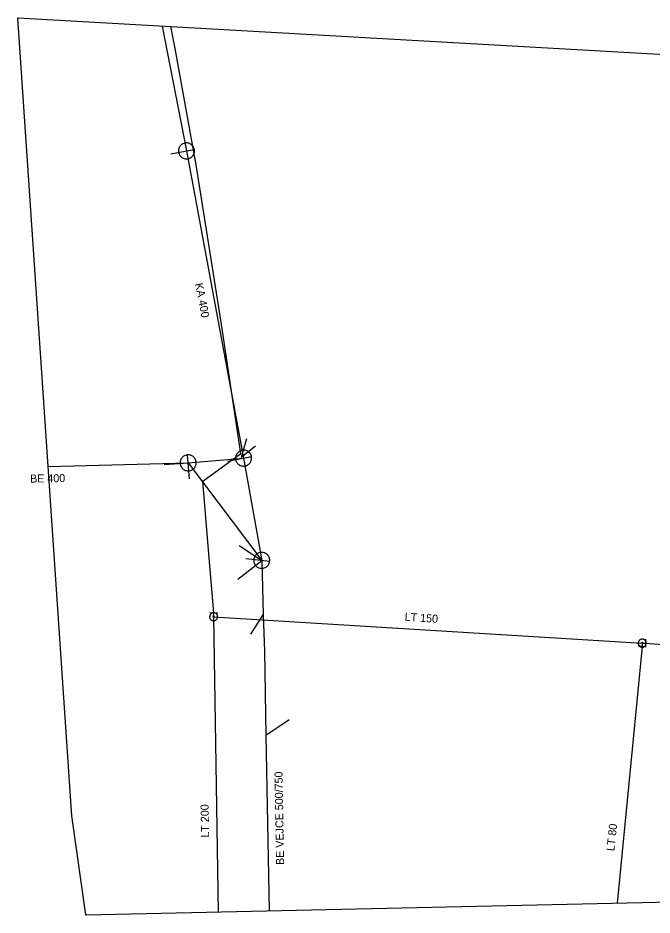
# Model space of a CAD drawing. Extents: x -716525 to -716349, y -954127 to -954015.
# Drawn here: x -716525 to -716445.8, y -954126.6 to -954014.6 of the extents above; entities that cross this region are included whole.
import ezdxf

# ---------------------------------------------------------------- set-up
doc = ezdxf.new("R2010")
doc.units = 0
for name, color, linetype in [('Vrstva 1', 7, 'Continuous'), ('Vrstva 11', 7, 'Continuous'), ('Vrstva 14', 7, 'Continuous'), ('Vrstva 17', 7, 'Continuous'), ('Vrstva 22', 7, 'Continuous'), ('Vrstva 34', 7, 'Continuous'), ('Vrstva 47', 7, 'Continuous'), ('Vrstva 63', 7, 'Continuous')]:
    doc.layers.add(name, color=color, linetype=linetype)

msp = doc.modelspace()

# ---------------------------------------------------------------- linework, layer by layer
at = {"layer": 'Vrstva 11'}
for points in [[(-716496.487, -954067.156), (-716497.136, -954069.488)], [(-716495.347, -954068.067), (-716497.136, -954069.488)], [(-716506.77, -954070.359), (-716503.76, -954070.149)], [(-716497.398, -954080.489), (-716494.565, -954082.325)], [(-716497.532, -954084.686), (-716494.565, -954082.325)], [(-716495.917, -954091.543), (-716494.395, -954089.144)], [(-716491.13, -954102.256), (-716494.039, -954104.18)]]:
    msp.add_lwpolyline(points, dxfattribs=at)
at = {"layer": 'Vrstva 14'}
for points in [[(-716506.995, -954015.599), (-716503.969, -954031.19)], [(-716503.969, -954031.19), (-716496.829, -954069.559)], [(-716503.76, -954070.149), (-716496.829, -954069.559)], [(-716496.829, -954069.559), (-716494.565, -954082.325)], [(-716521.234, -954070.59), (-716503.76, -954070.149)], [(-716503.76, -954070.149), (-716494.565, -954082.325)], [(-716494.565, -954082.325), (-716494.395, -954089.144), (-716494.227, -954093.666), (-716494.039, -954104.18), (-716493.649, -954126.119)], [(-716500.572, -954089.369), (-716500.552, -954088.87)], [(-716447.02, -954092.67), (-716447.05, -954093.092)], [(-716447.02, -954092.67), (-716446.614, -954092.66)]]:
    msp.add_lwpolyline(points, dxfattribs=at)
at = {"layer": 'Vrstva 17'}
for points in [[(-716500.552, -954088.87), (-716501.256, -954080.524), (-716501.92, -954072.44), (-716497.19, -954068.969), (-716499.646, -954052.587), (-716502.776, -954032.943), (-716505.399, -954018.397), (-716505.935, -954015.659)], [(-716500.572, -954089.369), (-716500.007, -954126.26)], [(-716500.572, -954089.369), (-716447.02, -954092.67)], [(-716447.05, -954093.092), (-716450.147, -954125.154)], [(-716446.614, -954092.66), (-716441.116, -954093.066), (-716435.876, -954093.455), (-716424.218, -954094.18), (-716409.455, -954095.1), (-716395.355, -954095.978), (-716387.266, -954096.485), (-716378.456, -954097.125), (-716369.476, -954097.505), (-716352.497, -954098.776)]]:
    msp.add_lwpolyline(points, dxfattribs=at)
at = {"layer": 'Vrstva 22'}
for points in [[(-716503.778, -954032.171), (-716503.673, -954032.145), (-716503.57, -954032.106), (-716503.472, -954032.057), (-716503.38, -954031.998), (-716503.295, -954031.929), (-716503.218, -954031.851), (-716503.151, -954031.764), (-716503.093, -954031.672), (-716503.045, -954031.573), (-716503.009, -954031.47), (-716502.984, -954031.363), (-716502.972, -954031.254), (-716502.97, -954031.144), (-716502.981, -954031.036), (-716503.004, -954030.928), (-716503.038, -954030.825), (-716503.083, -954030.724), (-716503.139, -954030.63), (-716503.206, -954030.543), (-716503.281, -954030.464), (-716503.365, -954030.393), (-716503.455, -954030.332), (-716503.553, -954030.281), (-716503.654, -954030.24), (-716503.759, -954030.212), (-716503.868, -954030.195), (-716503.978, -954030.19), (-716504.086, -954030.197), (-716504.195, -954030.216), (-716504.3, -954030.246), (-716504.401, -954030.287), (-716504.496, -954030.341), (-716504.586, -954030.403), (-716504.669, -954030.475), (-716504.743, -954030.556), (-716504.807, -954030.644), (-716504.862, -954030.74), (-716504.906, -954030.84), (-716504.939, -954030.944), (-716504.959, -954031.052), (-716504.969, -954031.161), (-716504.966, -954031.27), (-716504.951, -954031.379), (-716504.924, -954031.485), (-716504.886, -954031.588), (-716504.837, -954031.685), (-716504.778, -954031.777), (-716504.708, -954031.863), (-716504.63, -954031.939), (-716504.545, -954032.007), (-716504.452, -954032.066), (-716504.353, -954032.113), (-716504.25, -954032.15), (-716504.144, -954032.174), (-716504.035, -954032.187), (-716503.925, -954032.188), (-716503.816, -954032.178), (-716503.778, -954032.171)], [(-716505.932, -954031.571), (-716502.987, -954030.999)], [(-716502.763, -954070.064), (-716502.778, -954069.956), (-716502.805, -954069.85), (-716502.844, -954069.747), (-716502.893, -954069.65), (-716502.953, -954069.557), (-716503.022, -954069.473), (-716503.101, -954069.396), (-716503.187, -954069.329), (-716503.28, -954069.271), (-716503.379, -954069.224), (-716503.482, -954069.188), (-716503.589, -954069.164), (-716503.698, -954069.151), (-716503.807, -954069.15), (-716503.917, -954069.162), (-716504.023, -954069.185), (-716504.128, -954069.219), (-716504.227, -954069.264), (-716504.321, -954069.322), (-716504.407, -954069.387), (-716504.487, -954069.463), (-716504.557, -954069.547), (-716504.619, -954069.638), (-716504.67, -954069.735), (-716504.709, -954069.836), (-716504.738, -954069.942), (-716504.754, -954070.051), (-716504.759, -954070.16), (-716504.752, -954070.27), (-716504.733, -954070.377), (-716504.703, -954070.482), (-716504.66, -954070.583), (-716504.608, -954070.679), (-716504.545, -954070.769), (-716504.471, -954070.851), (-716504.391, -954070.924), (-716504.302, -954070.989), (-716504.207, -954071.043), (-716504.107, -954071.087), (-716504.002, -954071.119), (-716503.895, -954071.14), (-716503.786, -954071.149), (-716503.676, -954071.145), (-716503.568, -954071.13), (-716503.461, -954071.103), (-716503.359, -954071.065), (-716503.261, -954071.016), (-716503.169, -954070.956), (-716503.084, -954070.886), (-716503.008, -954070.809), (-716502.94, -954070.723), (-716502.883, -954070.629), (-716502.835, -954070.531), (-716502.799, -954070.428), (-716502.774, -954070.321), (-716502.762, -954070.212), (-716502.761, -954070.102), (-716502.763, -954070.064)], [(-716503.59, -954072.142), (-716503.844, -954069.153)], [(-716498.795, -954069.924), (-716495.846, -954069.376)], [(-716496.646, -954070.542), (-716496.54, -954070.516), (-716496.437, -954070.478), (-716496.338, -954070.43), (-716496.246, -954070.372), (-716496.161, -954070.303), (-716496.083, -954070.225), (-716496.015, -954070.139), (-716495.957, -954070.047), (-716495.908, -954069.949), (-716495.871, -954069.846), (-716495.845, -954069.74), (-716495.832, -954069.63), (-716495.83, -954069.521), (-716495.84, -954069.412), (-716495.862, -954069.304), (-716495.896, -954069.201), (-716495.94, -954069.1), (-716495.995, -954069.006), (-716496.061, -954068.918), (-716496.135, -954068.838), (-716496.219, -954068.767), (-716496.308, -954068.705), (-716496.406, -954068.653), (-716496.507, -954068.612), (-716496.612, -954068.582), (-716496.72, -954068.565), (-716496.83, -954068.559), (-716496.939, -954068.565), (-716497.047, -954068.583), (-716497.152, -954068.613), (-716497.254, -954068.653), (-716497.35, -954068.705), (-716497.44, -954068.767), (-716497.523, -954068.838), (-716497.598, -954068.919), (-716497.663, -954069.007), (-716497.719, -954069.102), (-716497.763, -954069.201), (-716497.797, -954069.305), (-716497.818, -954069.413), (-716497.829, -954069.522), (-716497.827, -954069.631), (-716497.812, -954069.741), (-716497.786, -954069.847), (-716497.749, -954069.949), (-716497.701, -954070.047), (-716497.642, -954070.14), (-716497.573, -954070.226), (-716497.496, -954070.303), (-716497.411, -954070.372), (-716497.319, -954070.431), (-716497.22, -954070.479), (-716497.118, -954070.517), (-716497.011, -954070.542), (-716496.903, -954070.556), (-716496.793, -954070.558), (-716496.684, -954070.548), (-716496.646, -954070.542)], [(-716494.673, -954083.319), (-716494.564, -954083.324), (-716494.455, -954083.318), (-716494.346, -954083.3), (-716494.242, -954083.271), (-716494.14, -954083.23), (-716494.043, -954083.178), (-716493.953, -954083.115), (-716493.871, -954083.044), (-716493.796, -954082.964), (-716493.731, -954082.876), (-716493.675, -954082.782), (-716493.631, -954082.681), (-716493.598, -954082.577), (-716493.576, -954082.47), (-716493.566, -954082.36), (-716493.568, -954082.251), (-716493.581, -954082.142), (-716493.607, -954082.036), (-716493.645, -954081.933), (-716493.693, -954081.835), (-716493.752, -954081.742), (-716493.82, -954081.657), (-716493.898, -954081.579), (-716493.983, -954081.511), (-716494.076, -954081.452), (-716494.174, -954081.404), (-716494.278, -954081.367), (-716494.383, -954081.341), (-716494.493, -954081.327), (-716494.602, -954081.326), (-716494.711, -954081.335), (-716494.818, -954081.357), (-716494.922, -954081.39), (-716495.022, -954081.435), (-716495.117, -954081.491), (-716495.204, -954081.556), (-716495.285, -954081.63), (-716495.356, -954081.713), (-716495.418, -954081.803), (-716495.47, -954081.9), (-716495.512, -954082.001), (-716495.541, -954082.106), (-716495.559, -954082.215), (-716495.565, -954082.324), (-716495.559, -954082.433), (-716495.541, -954082.541), (-716495.512, -954082.647), (-716495.47, -954082.749), (-716495.418, -954082.845), (-716495.357, -954082.935), (-716495.285, -954083.018), (-716495.205, -954083.093), (-716495.118, -954083.158), (-716495.023, -954083.213), (-716494.923, -954083.258), (-716494.818, -954083.292), (-716494.711, -954083.313), (-716494.673, -954083.319)], [(-716496.553, -954082.108), (-716493.571, -954082.433)]]:
    msp.add_lwpolyline(points, dxfattribs=at)
at = {"layer": 'Vrstva 34'}
for points in [[(-716501.051, -954088.85), (-716500.052, -954088.89)], [(-716446.552, -954093.139), (-716447.547, -954093.043)], [(-716446.614, -954092.16), (-716446.614, -954093.16)]]:
    msp.add_lwpolyline(points, dxfattribs=at)
at = {"layer": 'Vrstva 47'}
for points in [[(-716500.583, -954089.868), (-716500.531, -954089.867), (-716500.479, -954089.86), (-716500.428, -954089.847), (-716500.379, -954089.83), (-716500.331, -954089.807), (-716500.287, -954089.779), (-716500.246, -954089.747), (-716500.208, -954089.711), (-716500.174, -954089.672), (-716500.144, -954089.628), (-716500.119, -954089.582), (-716500.1, -954089.533), (-716500.085, -954089.484), (-716500.076, -954089.432), (-716500.072, -954089.38), (-716500.073, -954089.328), (-716500.08, -954089.276), (-716500.093, -954089.224), (-716500.11, -954089.176), (-716500.133, -954089.128), (-716500.161, -954089.084), (-716500.193, -954089.042), (-716500.229, -954089.004), (-716500.268, -954088.97), (-716500.312, -954088.941), (-716500.358, -954088.916), (-716500.407, -954088.896), (-716500.456, -954088.882), (-716500.508, -954088.873), (-716500.56, -954088.869), (-716500.612, -954088.87), (-716500.664, -954088.877), (-716500.716, -954088.889), (-716500.764, -954088.907), (-716500.812, -954088.93), (-716500.856, -954088.957), (-716500.898, -954088.989), (-716500.936, -954089.025), (-716500.97, -954089.065), (-716500.999, -954089.109), (-716501.024, -954089.155), (-716501.044, -954089.203), (-716501.058, -954089.253), (-716501.067, -954089.305), (-716501.071, -954089.357), (-716501.07, -954089.409), (-716501.063, -954089.461), (-716501.051, -954089.512), (-716501.033, -954089.561), (-716501.01, -954089.609), (-716500.983, -954089.653), (-716500.951, -954089.694), (-716500.915, -954089.732), (-716500.875, -954089.766), (-716500.831, -954089.796), (-716500.785, -954089.821), (-716500.737, -954089.84), (-716500.687, -954089.855), (-716500.635, -954089.864), (-716500.583, -954089.868)], [(-716500.573, -954089.45), (-716500.564, -954089.451), (-716500.556, -954089.449), (-716500.548, -954089.447), (-716500.54, -954089.444), (-716500.532, -954089.44), (-716500.525, -954089.436), (-716500.518, -954089.431), (-716500.512, -954089.425), (-716500.507, -954089.418), (-716500.501, -954089.411), (-716500.497, -954089.403), (-716500.494, -954089.395), (-716500.492, -954089.387), (-716500.49, -954089.379), (-716500.49, -954089.37), (-716500.489, -954089.361), (-716500.491, -954089.353), (-716500.493, -954089.345), (-716500.496, -954089.337), (-716500.5, -954089.329), (-716500.504, -954089.322), (-716500.509, -954089.315), (-716500.515, -954089.309), (-716500.522, -954089.303), (-716500.529, -954089.298), (-716500.537, -954089.294), (-716500.545, -954089.291), (-716500.553, -954089.289), (-716500.561, -954089.287), (-716500.57, -954089.287), (-716500.579, -954089.286), (-716500.587, -954089.288), (-716500.595, -954089.29), (-716500.603, -954089.293), (-716500.611, -954089.297), (-716500.618, -954089.3), (-716500.625, -954089.306), (-716500.631, -954089.312), (-716500.637, -954089.319), (-716500.642, -954089.326), (-716500.646, -954089.334), (-716500.649, -954089.342), (-716500.651, -954089.35), (-716500.653, -954089.358), (-716500.653, -954089.367), (-716500.654, -954089.376), (-716500.652, -954089.384), (-716500.65, -954089.392), (-716500.647, -954089.4), (-716500.643, -954089.408), (-716500.64, -954089.415), (-716500.634, -954089.422), (-716500.628, -954089.428), (-716500.621, -954089.433), (-716500.614, -954089.439), (-716500.606, -954089.443), (-716500.598, -954089.446), (-716500.59, -954089.448), (-716500.582, -954089.45), (-716500.573, -954089.45)], [(-716446.521, -954092.712), (-716446.52, -954092.66), (-716446.523, -954092.607), (-716446.533, -954092.556), (-716446.547, -954092.506), (-716446.567, -954092.457), (-716446.592, -954092.411), (-716446.622, -954092.368), (-716446.655, -954092.328), (-716446.692, -954092.292), (-716446.734, -954092.259), (-716446.779, -954092.231), (-716446.826, -954092.209), (-716446.875, -954092.191), (-716446.926, -954092.179), (-716446.977, -954092.171), (-716447.029, -954092.17), (-716447.082, -954092.173), (-716447.134, -954092.183), (-716447.183, -954092.197), (-716447.232, -954092.217), (-716447.278, -954092.242), (-716447.322, -954092.272), (-716447.362, -954092.305), (-716447.398, -954092.342), (-716447.43, -954092.384), (-716447.458, -954092.429), (-716447.481, -954092.476), (-716447.498, -954092.525), (-716447.51, -954092.576), (-716447.518, -954092.627), (-716447.519, -954092.679), (-716447.516, -954092.732), (-716447.507, -954092.784), (-716447.492, -954092.833), (-716447.472, -954092.882), (-716447.448, -954092.928), (-716447.418, -954092.972), (-716447.385, -954093.012), (-716447.347, -954093.048), (-716447.305, -954093.08), (-716447.26, -954093.108), (-716447.214, -954093.131), (-716447.164, -954093.148), (-716447.113, -954093.16), (-716447.062, -954093.168), (-716447.01, -954093.169), (-716446.957, -954093.166), (-716446.906, -954093.157), (-716446.856, -954093.142), (-716446.807, -954093.122), (-716446.761, -954093.098), (-716446.718, -954093.068), (-716446.678, -954093.035), (-716446.642, -954092.997), (-716446.609, -954092.955), (-716446.581, -954092.91), (-716446.559, -954092.864), (-716446.541, -954092.814), (-716446.529, -954092.763), (-716446.521, -954092.712)], [(-716446.938, -954092.676), (-716446.937, -954092.667), (-716446.938, -954092.659), (-716446.94, -954092.651), (-716446.942, -954092.643), (-716446.945, -954092.635), (-716446.95, -954092.627), (-716446.954, -954092.62), (-716446.96, -954092.613), (-716446.966, -954092.608), (-716446.973, -954092.602), (-716446.98, -954092.598), (-716446.988, -954092.594), (-716446.996, -954092.591), (-716447.004, -954092.589), (-716447.013, -954092.588), (-716447.022, -954092.587), (-716447.03, -954092.588), (-716447.038, -954092.59), (-716447.046, -954092.592), (-716447.054, -954092.595), (-716447.062, -954092.6), (-716447.069, -954092.604), (-716447.076, -954092.61), (-716447.082, -954092.616), (-716447.087, -954092.623), (-716447.091, -954092.63), (-716447.095, -954092.638), (-716447.098, -954092.646), (-716447.1, -954092.654), (-716447.101, -954092.663), (-716447.102, -954092.672), (-716447.101, -954092.68), (-716447.099, -954092.688), (-716447.097, -954092.696), (-716447.094, -954092.704), (-716447.09, -954092.712), (-716447.085, -954092.719), (-716447.079, -954092.726), (-716447.073, -954092.732), (-716447.066, -954092.737), (-716447.059, -954092.741), (-716447.051, -954092.745), (-716447.043, -954092.748), (-716447.035, -954092.75), (-716447.026, -954092.751), (-716447.017, -954092.752), (-716447.009, -954092.751), (-716447.001, -954092.749), (-716446.993, -954092.747), (-716446.985, -954092.744), (-716446.977, -954092.74), (-716446.97, -954092.735), (-716446.963, -954092.729), (-716446.958, -954092.723), (-716446.952, -954092.716), (-716446.948, -954092.709), (-716446.944, -954092.701), (-716446.941, -954092.693), (-716446.939, -954092.685), (-716446.938, -954092.676)]]:
    msp.add_lwpolyline(points, dxfattribs=at)
at = {"layer": 'Vrstva 63'}
msp.add_lwpolyline([(-716356.886, -954123.084), (-716516.511, -954126.626), (-716516.513, -954126.626), (-716516.515, -954126.625), (-716516.517, -954126.624), (-716516.519, -954126.623), (-716516.52, -954126.621), (-716516.521, -954126.619), (-716516.521, -954126.617), (-716518.281, -954114.225), (-716518.281, -954114.224), (-716525.024, -954014.594), (-716525.024, -954014.592), (-716525.023, -954014.59), (-716525.023, -954014.588), (-716525.022, -954014.587), (-716525.02, -954014.585), (-716525.019, -954014.584), (-716525.017, -954014.583), (-716525.015, -954014.583), (-716525.013, -954014.583), (-716418.454, -954020.591)], dxfattribs=at)

# ---------------------------------------------------------------- texts
at = {"layer": 'Vrstva 1'}
for s, rotation, p in [('KA 400', 281, (-716502.9, -954047.788)), ('BE 400', 1, (-716523.496, -954072.621)), ('LT 150', 356, (-716476.729, -954089.851)), ('BE VEJCE 500/750', 91, (-716491.765, -954120.36)), ('LT 200', 91, (-716501.135, -954116.949)), ('LT 80 ', 84, (-716450.51, -954118.675))]:
    msp.add_text(s, height=1, rotation=rotation, dxfattribs=at).set_placement(p)

doc.saveas('drawing.dxf')
